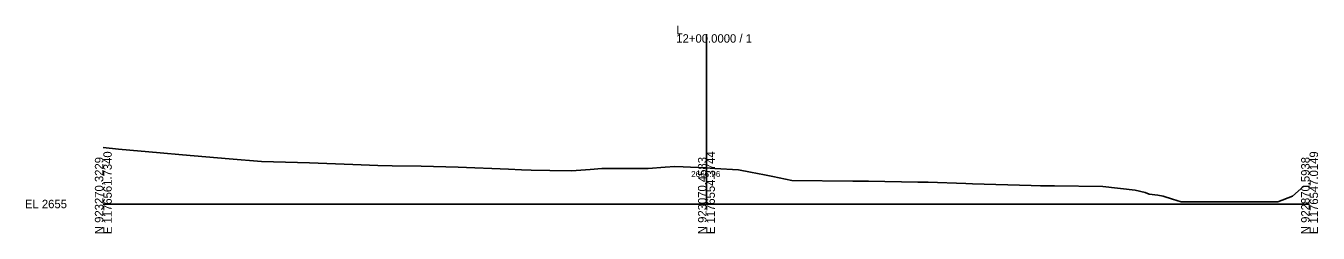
# Model space of a CAD drawing. Extents: x -26 to 1403, y -10 to 9563.
# Drawn here: x -25.7 to 402.8, y 1990.3 to 2059.2 of the extents above; entities that cross this region are included whole.
import ezdxf

# ---------------------------------------------------------------- set-up
doc = ezdxf.new("R2010")
doc.units = 0
for name, color, linetype in [('Exist Cross Section Cell', 7, 'Continuous'), ('Exist XS Center Line Elevation Label', 7, 'Continuous'), ('Exist XS Ground Line', 7, 'Continuous')]:
    doc.layers.add(name, color=color, linetype=linetype)

msp = doc.modelspace()

# ---------------------------------------------------------------- linework, layer by layer
at = {"layer": 'Exist Cross Section Cell'}
for p, q in [((200, 2000), (200, 2056.38)), ((0, 2000), (200, 2000)), ((200, 2000), (400, 2000))]:
    msp.add_line(p, q, dxfattribs=at)
at = {"layer": 'Exist XS Ground Line'}
for p, q in [((0, 2018.79), (5.03, 2018.17)), ((5.03, 2018.17), (18.84, 2016.97)), ((18.84, 2016.97), (26.22, 2016.3)), ((26.22, 2016.3), (41.78, 2015.01)), ((41.78, 2015.01), (52.41, 2014.1)), ((52.41, 2014.1), (68.37, 2013.67)), ((68.37, 2013.67), (82.71, 2013.12)), ((82.71, 2013.12), (90.98, 2012.79)), ((90.98, 2012.79), (95.8, 2012.73)), ((95.8, 2012.73), (105.42, 2012.6)), ((105.42, 2012.6), (117.63, 2012.24)), ((117.63, 2012.24), (134.38, 2011.56)), ((134.38, 2011.56), (138.64, 2011.4)), ((138.64, 2011.4), (141.84, 2011.24)), ((141.84, 2011.24), (148.06, 2011.11)), ((148.06, 2011.11), (155.3, 2011.02)), ((155.3, 2011.02), (161.4, 2011.51)), ((161.4, 2011.51), (165.28, 2011.79)), ((165.28, 2011.79), (168.06, 2011.8)), ((168.06, 2011.8), (180.72, 2011.79)), ((180.72, 2011.79), (186.27, 2012.26)), ((186.27, 2012.26), (189.51, 2012.51)), ((189.51, 2012.51), (192.27, 2012.36)), ((192.27, 2012.36), (199.71, 2011.97)), ((199.71, 2011.97), (202.77, 2011.8)), ((202.77, 2011.8), (210.62, 2011.36)), ((210.62, 2011.36), (214.55, 2010.56)), ((214.55, 2010.56), (219.28, 2009.65)), ((219.28, 2009.65), (222.02, 2009.11)), ((222.02, 2009.11), (228.35, 2007.78)), ((228.35, 2007.78), (248.56, 2007.62)), ((248.56, 2007.62), (253.78, 2007.6)), ((253.78, 2007.6), (270.14, 2007.28)), ((270.14, 2007.28), (272.59, 2007.24)), ((272.59, 2007.24), (273.5, 2007.2)), ((273.5, 2007.2), (286.06, 2006.77)), ((286.06, 2006.77), (288.22, 2006.71)), ((288.22, 2006.71), (307.72, 2006.1)), ((307.72, 2006.1), (310.72, 2006.07)), ((310.72, 2006.07), (315.36, 2006.01)), ((315.36, 2006.01), (331.46, 2005.86)), ((331.46, 2005.86), (342.13, 2004.65)), ((394.28, 2002.57), (398.13, 2005.91)), ((398.13, 2005.91), (400, 2005.86)), ((342.13, 2004.65), (345.48, 2003.77)), ((345.48, 2003.77), (346.75, 2003.3)), ((346.75, 2003.3), (349.66, 2002.93)), ((349.66, 2002.93), (351.47, 2002.65)), ((351.47, 2002.65), (354.57, 2001.66)), ((354.57, 2001.66), (357.45, 2000.76)), ((389.42, 2000.76), (394.28, 2002.57)), ((357.45, 2000.76), (357.98, 2000.76)), ((357.98, 2000.76), (389.06, 2000.76)), ((389.06, 2000.76), (389.42, 2000.76))]:
    msp.add_line(p, q, dxfattribs=at)

# ---------------------------------------------------------------- texts
at = {"layer": 'Exist Cross Section Cell'}
for s, p in [('L', (190, 2056.38)), ('12+00.0000 / 1', (190, 2053.58)), ('EL 2655', (-26, 1998.6))]:
    msp.add_text(s, height=2.8, dxfattribs=at).set_placement(p)
for s, p in [('N 923270.3229', (0, 1990)), ('E 1176561.7340', (2.8, 1990)), ('N 923070.4583', (200, 1990)), ('E 1176554.3744', (202.8, 1990)), ('N 922870.5938', (400, 1990)), ('E 1176547.0149', (402.8, 1990))]:
    msp.add_text(s, height=2.8, rotation=90, dxfattribs=at).set_placement(p)
at = {"layer": 'Exist XS Center Line Elevation Label'}
msp.add_text('2666.96', height=2, dxfattribs=at).set_placement((194.94, 2008.96))

doc.saveas('drawing.dxf')
